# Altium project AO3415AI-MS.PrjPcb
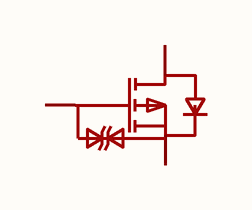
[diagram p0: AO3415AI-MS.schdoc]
1 sheet, 1 parts. Net scope: global (net labels, ports and power ports of the same name join across sheets).

## Sheet AO3415AI-MS.schdoc
size 127 x 101 mm

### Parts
Q?  ao3415ai-ms  [SOT-23-3_L2.9-W1.6-P1.90-LS2.8-BR]  (value not drawn)

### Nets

Not connected (* = marked no-connect by the designer): Q? 1(G) 2(S) 3(D)

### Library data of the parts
Q? = ao3415ai-ms: 数量:-;漏源电压(Vdss):20V;连续漏极电流(Id):4A;导通电阻(RDS(on)):41mΩ@4.5V;耗散功率(Pd):1W;阈值电压(Vgs(th)):900mV@250uA;; Manufacturer: MSKSEMI(美森科); AddInBom: yes; ModelId: 89cb27a44ab2466697082bb9fd73a7d0; ModelName: SOT-23-3L_L2.9-W1.6-H1.1-LS2.8-P0.95; ModelTransform: 114.173,110.236,0,90,0,0,0,0,0; Drain to Source Voltage: 20V; Current - Continuous Drain(Id): 4A; Pd - Power Dissipation: 1W; Gate Charge(Qg): 11nC@4.5V; Input Capacitance(Ciss): 905pF; Reverse Transfer Capacitance (Crss@Vds): 115pF; Type: P沟道; Output Capacitance(Coss): 150pF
